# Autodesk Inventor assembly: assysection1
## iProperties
Author: Administrator
Created: 2001-01
Part Number: assysection1
Document SubType Name: Assembly
Designer: Administrator
Control State: 0
Master: False
Checked Out: False
PropertySet Name: Design Tracking Control
Shininess: 0.0
PropertySet Name: _Private Model Information
Density: 0.0
Volumn: 0.0
Area: 0.0
PropertySet Name: Model Information
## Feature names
1. 珖
2. 珖
